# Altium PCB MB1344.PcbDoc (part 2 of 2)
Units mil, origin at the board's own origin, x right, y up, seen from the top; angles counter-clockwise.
Board outline 2760.94 x 3253.06 mil, 2 copper layers (Top Layer, Bottom Layer), stack 61.811 mil thick; 133 components, 124 nets, 521 pads, 490 vias.
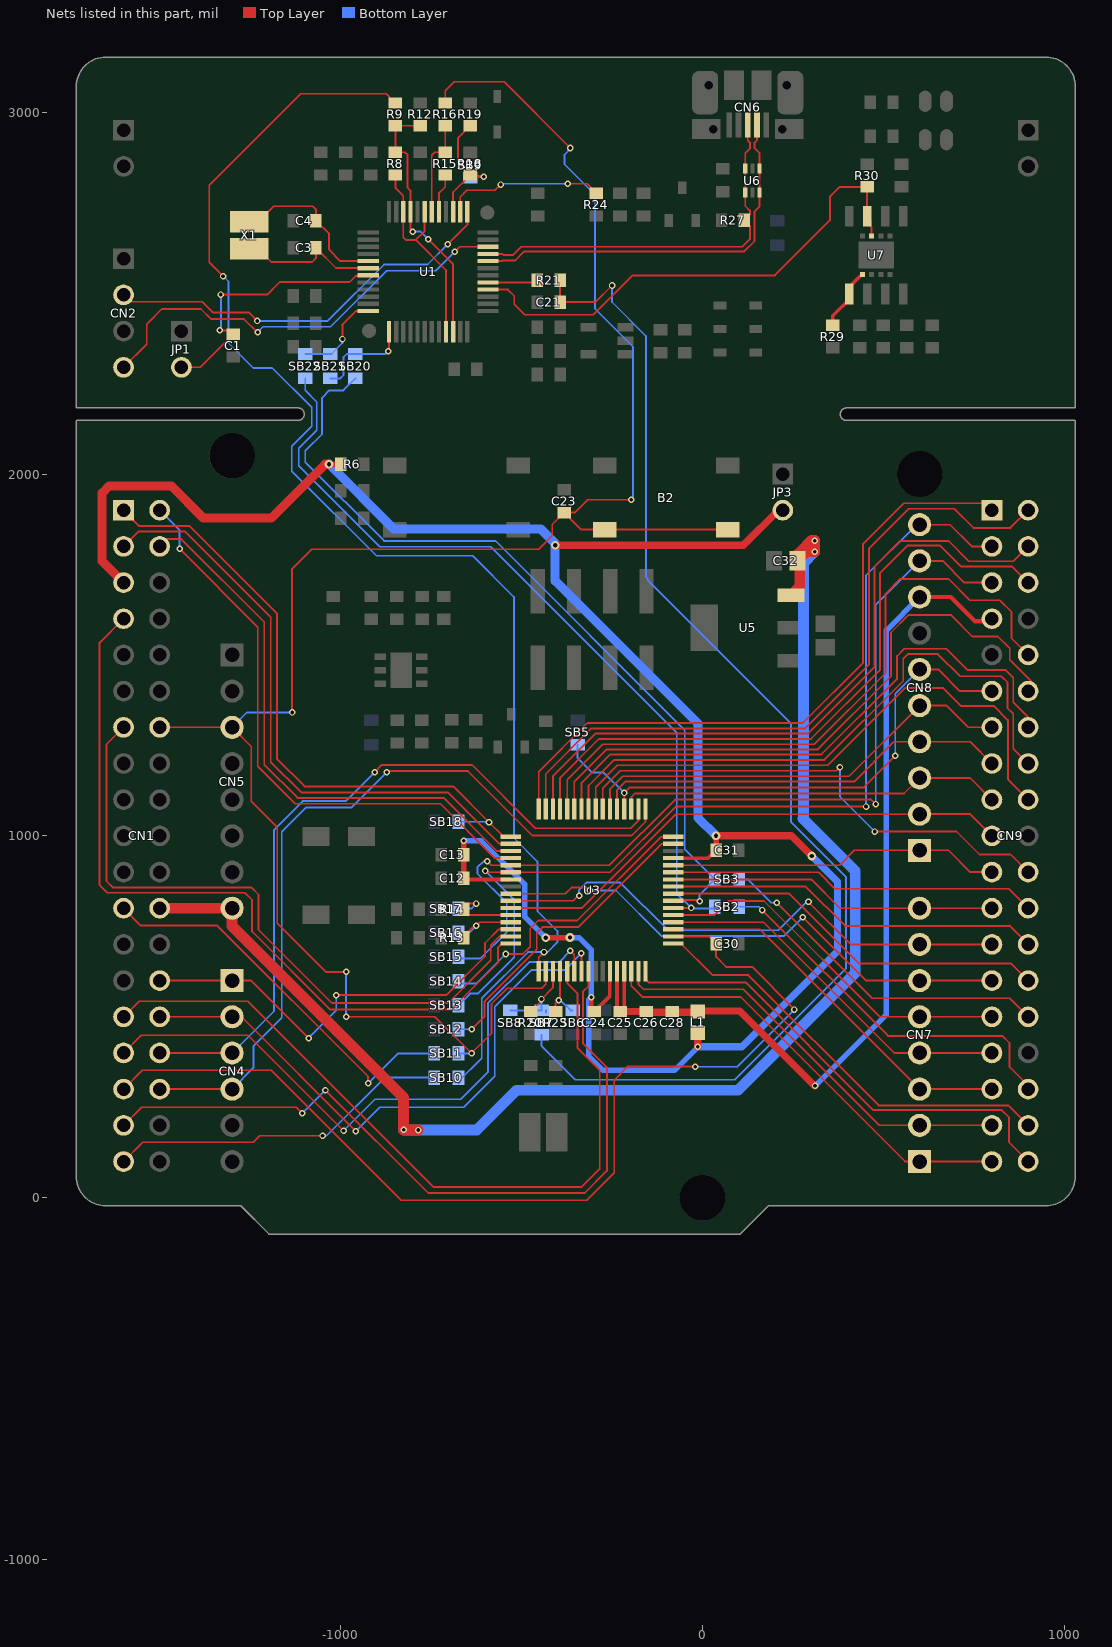
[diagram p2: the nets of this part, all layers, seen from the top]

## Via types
v1: diameter 18, hole 10, Top Layer to Bottom Layer, tented both sides, 474 vias
v2: diameter 24, hole 12, Top Layer to Bottom Layer, tented both sides, 12 vias
v3: diameter 23.62, hole 7.87, Top Layer to Bottom Layer, 4 vias

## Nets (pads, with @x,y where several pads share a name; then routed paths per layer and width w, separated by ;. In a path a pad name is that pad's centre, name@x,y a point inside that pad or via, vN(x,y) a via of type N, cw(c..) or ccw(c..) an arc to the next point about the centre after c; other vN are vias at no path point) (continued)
NetR18_1: R18.1 R19.2 SB9.2 U1.39 | length 356.5
  Top Layer w5: U1.39@-689.1,2724.35 -689.1,2779.4 R18.1@-646.5,2822 ; R19.2@-642,2962.5 -676,2928.5 -676,2860.5 R18.1@-642,2826.5 -637.5,2822 v1(-605,2822)
  Bottom Layer w5: SB9.2@-642,2819.25 -639.25,2822 v1(-605,2822)
NetR21_1: R21.1 U1.29 | length 138.9
  Top Layer w5: U1.29@-592.65,2529.47 -463.02,2529.47 R21.1@-456.5,2536
NetSB20_2: SB20.2 SB21.2 U1.13 | length 276.1
  Top Layer w5: v1(-868,2339) -866.27,2340.73 U1.13@-866.27,2393.65
  Bottom Layer w5: SB21.2@-1028.5,2264.25 -1000.75,2264.25 -992,2273 -992,2323 -983.25,2331.75 SB20.2@-959,2331.75 -875.25,2331.75 v1(-868,2339)
NetSB21_1: SB21.1 SB22.2 U1.12 | length 254.6
  Top Layer w5: v1(-995,2373) -995,2411 -996,2412 -957.27,2450.73 U1.12@-923.35,2450.73
  Bottom Layer w5: SB22.2@-1098,2331.75 SB21.1@-1028.5,2331.75 -1025.25,2331.75 -995,2362 v1(-995,2373)
PA0: CN1.37 SB10.1 | length 954.3
  Top Layer w5: CN1.37@-1600,100 -1547,153 -1242,153 -1224,171 v1(-1050,171)
  Bottom Layer w5: v1(-1050,171) -1039,171 -878,332 SB10.1@-741.75,332
PA1: CN1.23 SB11.1 | length 1104.1
  Top Layer w5: CN1.23@-1600,800 -1552,752 -1341,752 -924,335 v1(-924,316)
  Bottom Layer w5: v1(-924,316) -841.29,398.71 SB11.1@-741.75,398.71
PA2: R20.2 SB7.2 SB8.1 U3.3 | length 261.9
  Top Layer w5: R20.2@-475,514.46 -445,544.46 v1(-445,549) -413.27,580.73 U3.3@-413.27,625.59
  Bottom Layer w5: SB8.1@-531,517.5 SB7.2@-444.67,517.5 -444.67,548.67 v1(-445,549) ; SB7.2@-432.33,511.75 SB7.2@-432.33,519
PA3: R23.1 SB6.1 U3.4 | length 166.7
  Top Layer w5: R23.1@-406,514.46 -406,537 v1(-397,546) -393.58,549.42 U3.4@-393.58,625.59
  Bottom Layer w5: v1(-397,546) -393,546 -364.5,517.5 SB6.1@-358.33,517.5
PA4: CN1.29 U3.5 | length 2149.8
  Top Layer w5: CN1.29@-1600,500 -1557,543 -1257,543 -744,30 -334,30 -284,80 -284,352 -345,413 -345,564 -373.9,592.9 U3.5@-373.9,625.59
PA5: CN1.31 U3.6 | length 1742.7
  Top Layer w5: CN1.31@-1600,400 -1551,449 -1256,449 v1(-992,185) ; v1(-365,682) -354.21,671.21 U3.6@-354.21,625.59
  Bottom Layer w5: v1(-992,185) -905,272 -668,272 -593,347 -593,537 -479,651 -396,651 v1(-365,682)
PA6: CN1.30 CN4.2 U3.7 | length 1662.3
  Top Layer w5: CN1.30@-1500,500 CN4.2@-1300,500 -1274,500 v1(-958,184) ; U3.7@-334.53,625.59 v1(-334.53,675.47)
  Bottom Layer w5: v1(-958,184) -892,250 -660,250 -574,336 -574,528 -473,629 -381,629 v1(-334.53,675.47)
PA7: CN1.35 U3.8 | length 2118.4
  Top Layer w5: CN1.35@-1600,200 -1550,250 -1123,250 v1(-1106,233) ; v1(-1042,297) -758,13 -325,13 -264,74 -264,360 -330,426 -330,570 -314.84,585.16 U3.8@-314.84,625.59
  Bottom Layer w5: v1(-1106,233) v1(-1042,297)
PB0: SB12.1 U3.31 | length 857.3
  Top Layer w5: v1(-638,465.43) -602,501.43 -602,542.4 -458,686.4 -458,732 -442,748 -343,748 -113.05,977.95 U3.31@-80.59,977.95 U3.31@-80.17,978.37
  Bottom Layer w5: SB12.1@-674.25,465.43 v1(-638,465.43)
PB1: SB14.1 U3.32 | length 792.4
  Top Layer w5: v1(-544,673.5) -496.5,673.5 -476,694 -476,744 -454,766 -346,766 -114.36,997.64 U3.32@-80.59,997.64 U3.32@-80.59,999.07
  Bottom Layer w5: SB14.1@-674.25,592 -625.5,592 v1(-544,673.5)
PB2: CN1.34 CN4.4 U3.33 | length 2177.5
  Top Layer w5: CN1.34@-1500,300 CN4.4@-1300,300 ; v1(-873,1176) -875,1176 -878,1179 -648,1179 -470,1001 -196,1001 -157.36,1039.64 U3.33@-157.36,1074.41
  Bottom Layer w5: CN4.4@-1300,300 -1241,359 -1241,419 -1163,497 -1163,1011 -1096,1078 -971,1078 v1(-873,1176)
PB3: CN1.32 CN4.3 U3.34 | length 2059.8
  Top Layer w5: CN1.32@-1500,400 CN4.3@-1300,400 ; v1(-906,1176) -886,1196 -637,1196 -462,1021 -198,1021 -177.05,1041.95 U3.34@-177.05,1074.41
  Bottom Layer w5: CN4.3@-1300,400 -1184,516 -1184,1017 -1105,1096 -986,1096 v1(-906,1176)
PB4: CN8.3 CN9.17 U3.35 | length 1076.3
  Top Layer w5: U3.35@-196.73,1074.41 -196.73,1107.27 -187,1117 557,1117 CN8.3@600,1160 740,1160 CN9.17@800,1100
PB5: CN8.6 CN9.11 SB5.1 U3.36 | length 1533.4
  Top Layer w5: U3.36@-216.42,1074.41 v1(-216.42,1118.58) -201,1134 446,1134 v1(533,1221) ; CN8.6@600,1460 651,1460 711,1400 CN9.11@800,1400
  Bottom Layer w5: SB5.1@-345,1252.25 -345,1215 -305,1175 -272.83,1175 v1(-216.42,1118.58) ; v1(533,1221) 533,1393 CN8.6@600,1460
PB6: CN8.4 CN9.15 U3.37 | length 1168.6
  Top Layer w5: U3.37@-236.1,1074.41 -236.1,1126.9 -213,1150 419,1150 529,1260 CN8.4@600,1260 740,1260 CN9.15@800,1200
PB7: CN8.5 CN9.13 U3.38 | length 1231
  Top Layer w5: U3.38@-255.79,1074.41 -255.79,1129.21 -220,1165 405,1165 CN8.5@600,1360 675,1360 735,1300 CN9.13@800,1300
PC0: CN8.9 CN9.5 SB15.2 U3.53 | length 2515.9
  Top Layer w5: v1(-595,930) -583.9,918.9 U3.53@-529.41,918.9 -257.1,918.9 -75.63,1100.37 466.63,1100.37 v1(479,1088) ; CN8.9@600,1760 664,1760 724,1700 CN9.5@800,1700
  Bottom Layer w5: SB15.2@-674.25,661 -614,661 -541,734 -541,815 -622,896 -622,913 -605,930 v1(-595,930) ; v1(479,1088) 479,1639 CN8.9@600,1760
PC1: CN8.10 CN9.3 SB13.2 U3.54 | length 2679.1
  Top Layer w5: v1(-600,903) -596.21,899.21 U3.54@-529.41,899.21 -529.25,899.37 -255.63,899.37 -74,1081 v1(452,1081) ; CN8.10@600,1860 684,1860 744,1800 CN9.3@800,1800
  Bottom Layer w5: SB13.2@-674.25,532.14 -642.39,564 -621,564 -520,665 -520,823 v1(-600,903) ; v1(452,1081) 452,1720 592,1860 CN8.10@600,1860
PC2: CN7.6 CN9.27 U3.57 | length 1485.9
  Top Layer w5: U3.57@-529.41,840.16 -378.84,840.16 -362,857 -320,857 v1(-312,849) ; v1(277,775) 277.33,775 452.33,600 CN7.6@600,600 CN9.27@800,600
  Bottom Layer w5: v1(-312,849) -239,849 -113,723 225,723 v1(277,775)
PC3: CN7.7 CN9.25 U3.58 | length 1497.2
  Top Layer w5: U3.58@-529.41,820.47 -357.53,820.47 -344,834 v1(-341,834) ; v1(293,818) 293,817 410,700 CN7.7@600,700 CN9.25@800,700
  Bottom Layer w5: v1(-341,834) -341,851 -321,871 -227,871 -95,739 209,739 288,818 v1(293,818)
PC4: CN8.2 CN9.19 U3.59 | length 1462.1
  Top Layer w5: U3.59@-529.41,800.79 -332.81,800.79 -292.63,840.98 -292.63,841.37 -74.37,1059.63 600,1059.63 CN8.2@600,1060 740,1060 CN9.19@800,1000
PC5: R14.1 SB17.1 U3.60 | length 232.9
  Top Layer w5: v1(-625,813) -643.5,813 R14.1@-659.5,797 -643.61,781.1 U3.60@-529.41,781.1
  Bottom Layer w5: SB17.1@-674.25,799 -639,799 v1(-625,813)
PC6: R13.1 SB16.1 U3.61 | length 207.7
  Top Layer w5: R13.1@-659.5,719 -659.5,723.5 -631,752 v1(-625,752) -615.58,761.42 U3.61@-529.41,761.42
  Bottom Layer w5: SB16.1@-674.25,732.28 -644.72,732.28 v1(-625,752)
PC7: CN1.28 CN4.1 U3.62 | length 1207.9
  Top Layer w5: CN1.28@-1500,600 CN4.1@-1300,600 -1247,600 v1(-1088,441) ; v1(-1012,560) -708,560 -601,667 -601,704 -563.27,741.73 U3.62@-529.41,741.73
  Bottom Layer w5: v1(-1088,441) -1088,442 -1012,518 v1(-1012,560)
PD0: CN9.26 U3.25 | length 1046.8
  Top Layer w5: U3.25@-80.59,859.84 285.16,859.84 394,751 849,751 CN9.26@900,700
PD1: CN7.8 CN9.23 U3.26 | length 913.5
  Top Layer w5: U3.26@-80.59,879.53 300.47,879.53 380,800 CN7.8@600,800 CN9.23@800,800
PD2: CN9.24 U3.27 | length 1021.7
  Top Layer w5: U3.27@-80.59,899.21 320.79,899.21 366,854 846,854 CN9.24@900,800
PD3: CN8.1 CN9.21 U3.28 | length 922.5
  Top Layer w5: U3.28@-80.59,918.9 378.9,918.9 420,960 CN8.1@600,960 680,960 740,900 CN9.21@800,900
PD4: CN9.6 U3.45 | length 1844.8
  Top Layer w5: U3.45@-393.58,1074.41 -393.58,1160.42 -286,1268 300,1268 491,1459 491,1727 566.26,1802.26 656.74,1802.26 715,1744 856,1744 CN9.6@900,1700
PD5: CN9.4 U3.46 | length 1875.5
  Top Layer w5: U3.46@-413.27,1074.41 -413.27,1164.73 -295,1283 292,1283 475,1466 475,1743 547.14,1815.14 679.86,1815.14 736,1759 859,1759 CN9.4@900,1800
PD6: CN9.2 U3.47 | length 1963.5
  Top Layer w5: U3.47@-432.95,1074.41 -432.95,1171.05 -307,1297 284,1297 460,1473 460,1794 570,1904 696,1904 749,1851 851,1851 CN9.2@900,1900
PD7: CN9.1 U3.48 | length 1862.8
  Top Layer w5: U3.48@-452.64,1074.41 -452.64,1177.36 -318,1312 277,1312 444,1479 444,1807 556,1919 781,1919 CN9.1@800,1900
PE0: CN7.3 CN9.33 U3.19 | length 1063.6
  Top Layer w5: U3.19@-80.59,741.73 158.27,741.73 CN7.3@600,300 CN9.33@800,300
PE1: CN7.4 CN9.31 U3.20 | length 1030.3
  Top Layer w5: U3.20@-80.59,761.42 168.58,761.42 530,400 CN7.4@600,400 CN9.31@800,400
PE2: CN7.5 CN9.29 U3.21 | length 1029.3
  Top Layer w5: U3.21@-80.59,781.1 33.1,781.1 72,820 170,820 490,500 CN7.5@600,500 CN9.29@800,500
PE3: CN9.34 SB2.2 | length 1051.5
  Top Layer w5: v1(165,795) 513,447 829,447 848.5,427.5 848.5,361.5 900,310 CN9.34@900,300
  Bottom Layer w5: SB2.2@101.75,804 156,804 v1(165,795)
PE4: CN9.30 SB3.2 | length 955.5
  Top Layer w5: v1(205,815) 469,551 849,551 CN9.30@900,500
  Bottom Layer w5: SB3.2@101.75,879.53 125.47,879.53 190,815 v1(205,815)
PE5: CN9.28 U3.24 | length 1080.4
  Top Layer w5: U3.24@-80.59,840.16 -80.59,840.37 239.63,840.37 433,647 853,647 CN9.28@900,600
PE6: CN1.13 U3.63 | length 1859.3
  Top Layer w5: CN1.13@-1600,1300 -1647,1253 -1647,875 -1629,857 -1246,857 -1227,838 -1227,741 -1024,538 -703,538 -585,656 -585,698 -560.95,722.05 U3.63@-529.41,722.05
PE7: CN1.7 U3.64 | length 2193.5
  Top Layer w5: CN1.7@-1600,1600 -1666,1534 -1666,864 -1645,843 -1265,843 -1245,823 -1245,736 -1029,520 -695,520 -565,650 -565,692 -554.64,702.36 U3.64@-529.41,702.36
PF0: CN9.22 U3.39 | length 1432
  Top Layer w5: U3.39@-275.47,1074.41 -275.47,1131.53 -227,1180 370,1180 v1(380,1190) ; v1(476,1012) 702,1012 765.5,948.5 851.5,948.5 CN9.22@900,900 CN9.22@900,907
  Bottom Layer w5: v1(380,1190) 380,1108 v1(476,1012)
PF1: CN9.18 U3.40 | length 1593.2
  Top Layer w5: U3.40@-295.16,1074.41 -295.16,1134.84 -235,1195 346,1195 560,1409 664,1409 714,1359 805,1359 844,1320 844,1156 CN9.18@900,1100
PF4: CN9.16 U3.41 | length 1689.3
  Top Layer w5: U3.41@-314.84,1074.41 -314.84,1139.16 -244,1210 337,1210 555,1428 555,1490 567.26,1502.26 650.74,1502.26 712,1441 826,1441 843,1424 843,1353 859,1337 859,1241 CN9.16@900,1200
PF5: CN9.14 U3.42 | length 1642.5
  Top Layer w5: U3.42@-334.53,1074.41 -334.53,1145.47 -255,1225 329,1225 538,1434 538,1497 558,1517 674,1517 733,1458 838,1458 859.1,1436.9 859.1,1368.9 900,1328 CN9.14@900,1300
PF6: CN9.12 U3.43 | length 1712
  Top Layer w5: U3.43@-354.21,1074.41 -354.21,1149.79 -265,1239 319,1239 521,1441 521,1562 569,1610 687,1610 746,1551 816,1551 849,1518 849,1487 909.1,1426.9 CN9.12@909.1,1409.1
PF7: CN9.10 U3.44 | length 1842.5
  Top Layer w5: U3.44@-373.9,1074.41 -373.9,1155.1 -276,1253 309,1253 506,1450 506,1669 547,1710 680,1710 739,1651 822,1651 854,1619 854,1546 CN9.10@900,1500
PG0: CN7.1 CN9.37 U3.14 | length 1237.8
  Top Layer w5: U3.14@-196.73,625.59 -196.73,585.73 -166,555 105,555 560,100 CN7.1@600,100 CN9.37@800,100
PG1: CN7.2 CN9.35 U3.15 | length 1174.2
  Top Layer w5: U3.15@-177.05,625.59 -177.05,590.05 -163,576 113,576 489,200 CN7.2@600,200 CN9.35@800,200
PG2: CN9.38 U3.16 | length 1328.5
  Top Layer w5: U3.16@-157.36,625.59 -157.36,603.36 -149,595 119,595 471.74,242.26 826.74,242.26 847,222 847,153 CN9.38@900,100
PG3: CN9.36 U3.17 | length 1188.7
  Top Layer w5: U3.17@-80.59,702.36 -59.36,702.36 27.87,615.13 126.87,615.13 486.86,255.14 844.86,255.14 CN9.36@900,200
PG4: CN1.1 SB18.1 U3.49 | length 1764.5
  Top Layer w5: CN1.1@-1600,1900 -1556,1856 -1417,1856 -1176,1615 -1176,1213 -1099.63,1136.63 -688.63,1136.63 v1(-590,1038) -549.64,997.64 U3.49@-529.41,997.64
  Bottom Layer w5: SB18.1@-674.25,1039 -591,1039 v1(-590,1038)
PG5: CN1.3 U3.50 | length 1679.4
  Top Layer w5: CN1.3@-1600,1800 -1559,1841 -1430,1841 -1193,1604 -1193,1204 -1109,1120 -704,1120 -561.95,977.95 U3.50@-529.41,977.95
PG6: CN1.4 U3.51 | length 1566.6
  Top Layer w5: CN1.4@-1500,1800 -1480,1820 -1440,1820 -1211,1591 -1211,1197 -1119,1105 -715,1105 -568.27,958.27 U3.51@-529.41,958.27
PG7: CN1.2 U3.52 | length 1624.8
  Top Layer w5: v1(-1445,1793) -1229,1577 -1229,1192 -1126,1089 -724,1089 -573.58,938.58 U3.52@-529.41,938.58
  Bottom Layer w5: CN1.2@-1500,1900 -1445,1845 v1(-1445,1793)
PWR_ENN: R30.2 U1.28 U7.3 | length 1414.9
  Top Layer w5: U1.28@-592.65,2509.79 -537.79,2509.79 -520,2492 -520,2469 -491,2440 -302,2440 -193,2549 200,2549 352,2701 352,2766 379.5,2793.5 R30.2@455,2793.5 U7.3@455,2712.28 455,2711.3 464,2702.3 464,2684 467.2,2680.8 U7.3@467.2,2658.15
SET: R29.2 U7.5 | length 168.3
  Top Layer w10: R29.2@360,2411.5 360,2437 405,2482 405,2516 U7.5@436.91,2547.91
STLINK_SWCLK: CN2.2 U1.37 | length 1125.5
  Top Layer w5: CN2.2@-1600,2495 -1581,2476 -1382,2476 -1352,2446 -1253,2446 v1(-1230,2423) ; v1(-704,2635) -649.73,2689.27 U1.37@-649.73,2724.35
  Bottom Layer w5: v1(-1230,2423) -1036,2423 -880,2579 -760,2579 v1(-704,2635)
STLINK_SWDIO: CN2.4 U1.34 | length 1230.5
  Top Layer w5: CN2.4@-1600,2295 -1536,2359 -1536,2414 -1494,2456 -1386,2456 -1358,2428 -1267,2428 -1231,2392 v1(-1229.6,2392) ; v1(-685,2614) -671.1,2627.9 U1.34@-592.65,2627.9
  Bottom Layer w5: v1(-1229.6,2392) -1214.6,2407 -1028,2407 -873,2562 -737,2562 v1(-685,2614)
STLINK_USB_D_N: CN6.2 U1.32 U6.1 U6.6 | length 1094.8
  Top Layer w5: U1.32@-592.65,2588.53 -554.47,2588.53 -553,2590 -517.79,2590 -492.66,2615.13 115.13,2615.13 144,2644 144,2726 157.69,2739.69 U6.6@157.69,2777.54 U6.1@157.69,2844.46 157.69,2886.31 143.87,2900.13 143.87,2915.87 150.59,2922.59 CN6.2@150.59,2965
STLINK_USB_D_P: CN6.3 R27.2 U1.33 U6.3 U6.4 | length 1085.1
  Top Layer w5: U1.33@-592.65,2608.21 -553,2608.21 -549.79,2605 -524,2605 -501,2628 109.79,2628 131.13,2649.33 131.13,2685.37 R27.2@115.5,2701 131.13,2716.63 131.13,2727.87 118.31,2740.69 U6.4@118.31,2777.54 U6.3@118.31,2844.46 118.31,2886.31 131,2899 131,2916 125,2922 CN6.3@125,2965
STLK_OSC_IN: C4.1 U1.5 X1.2 | length 453
  Top Layer w5: X1.2@-1252,2697.4 -1227.6,2697.4 -1185,2740 -1077,2740 -1068.5,2731.5 C4.1@-1068.5,2700 -1032,2663.5 -1032,2620 -1000.53,2588.53 U1.5@-923.35,2588.53
STLK_OSC_OUT: C3.1 U1.6 X1.1 | length 399.9
  Top Layer w5: X1.1@-1252,2622.6 -1228.6,2622.6 -1192,2586 -1079,2586 -1068.5,2596.5 C3.1@-1068.5,2625 -1012.88,2569.37 -923.89,2569.37 U1.6@-923.35,2568.84
STLK_RST: C1.2 JP1.2 U1.7 | length 752.2
  Top Layer w5: JP1.2@-1440,2295 -1388.5,2295 C1.2@-1297,2386.5 -1307.5,2397 v1(-1334,2397) ; v1(-1331,2496) -1203,2496 -1168.37,2530.63 -975.37,2530.63 -958.87,2547.13 -925.39,2547.13 U1.7@-923.35,2549.16
  Bottom Layer w5: v1(-1334,2397) -1331,2400 v1(-1331,2496)
SWIM: R8.1 R9.2 R12.1 U1.22 U1.45 | length 731.8
  Top Layer w5: v1(-801,2670) -807.21,2676.21 U1.45@-807.21,2724.35 -807.21,2783.21 -815,2791 -815,2882 -822.5,2889.5 R8.1@-848.5,2889.5 R9.2@-848.5,2962.5 R12.1@-779.67,2962.5 ; v1(-758,2649) -689.1,2580.1 U1.22@-689.1,2393.65
  Bottom Layer w5: v1(-801,2670) -779,2670 v1(-758,2649)
SWIM_IN: R8.2 U1.21 U1.43 U1.46 | length 594.5
  Top Layer w5: R8.2@-848.5,2826.5 -848.5,2790.6 -826.9,2769 U1.46@-826.9,2724.35 -826.9,2653.9 -819.95,2646.95 -792.05,2646.95 ; U1.43@-767.84,2724.35 -767.84,2671.16 -792.05,2646.95 ; U1.21@-708.79,2393.65 -708.79,2563.69 -792.05,2646.95
SWIM_RST: R15.1 R16.2 U1.42 | length 270.4
  Top Layer w5: U1.42@-748.16,2724.35 -748.16,2880.84 -739.5,2889.5 R15.1@-710.83,2889.5 R16.2@-710.83,2962.5
SWIM_RST_IN: R15.2 U1.41 | length 109.5
  Top Layer w5: U1.41@-728.47,2724.35 -728.47,2775.53 -710.83,2793.17 R15.2@-710.83,2826.5
T_MCO: C21.2 R21.2 SB7.1 | length 3417.5
  Top Layer w5: R21.2@-393.5,2536 C21.2@-393.5,2475 -296,2475 v1(-250,2521)
  Bottom Layer w5: SB7.1@-444.67,450 -444.67,418.67 -352,326 89,326 397,634 397,886 245,1038 245,1310 -151,1706 -151,1710.19 -156,1715.19 -156,2381.31 -250,2475.31 v1(-250,2521)
T_NRST: B2.1 B2.2 C23.2 CN1.14 CN5.3 R16.1 SB11.2 U3.2 | length 5566.6
  Top Layer w5: CN1.14@-1500,1300 CN5.3@-1300,1300 -1247,1247 -1247,1096 -1175,1024 -1175,758 -1041,624 v1(-985,624) ; v1(-1134,1341) -1134,1738 -1080,1792 -453,1792 -415,1830 -415,1860.5 C23.2@-382,1893.5 ; v1(-985,500) -739.57,500 v1(-638.29,398.71) -583,454 -583,536 -540,579 -444,579 -443,580 -432.95,590.08 U3.2@-432.95,625.59 ; R16.1@-710.83,3025.5 -710.83,3059 -685.83,3084 -548,3084 v1(-365,2901) ; v1(-197,1929) -317,1929 -352.5,1893.5 C23.2@-382,1893.5 ; B2.1@70.28,1846.42 B2.2@-270.28,1846.42 -334.91,1846.42 C23.2@-382,1893.5
  Bottom Layer w5: CN5.3@-1300,1300 -1259,1341 v1(-1134,1341) ; v1(-985,500) v1(-985,624) ; SB11.2@-674.25,398.71 v1(-638.29,398.71) ; v1(-365,2901) -365,2898.99 -381.37,2882.62 -381.37,2856.22 -297,2771.84 -297,2456.49 -192,2351.49 -192,1934 v1(-197,1929)
T_SWIM: R9.1 SB10.2 U3.1 | length 3946.5
  Top Layer w5: v1(-1325,2547) -1363,2585 -1363,2798 -1110,3051 -874,3051 R9.1@-848.5,3025.5 ; U3.1@-452.64,625.59 -452.64,664.36 v1(-438,679)
  Bottom Layer w5: v1(-1325,2547) -1310,2532 -1310,2362 -1241,2293 -1189,2293 -1080,2184 -1080,2132 -1135,2077 -1135,2008 -901,1774 -635,1774 -521,1660 -521,994 -456,929 -456,792 -401,737 -401,706 -428,679 v1(-438,679) -482,679 -610,551 -610,385.6 -674.25,321.35 SB10.2@-674.25,316
T_VCP_RX: SB2.1 SB22.1 U3.22 | length 2243.7
  Top Layer w5: U3.22@-80.59,800.79 v1(-31.21,800.79)
  Bottom Layer w5: SB22.1@-1098,2264.25 -1098,2231 -1066,2199 -1066,2121 -1116,2071 -1116,2023 -892,1799 -585,1799 -71,1285 -71,840.57 v1(-31.21,800.79) -30.05,799.63 29.88,799.63 SB2.1@34.25,804
T_VCP_TX: SB3.1 SB20.1 U3.23 | length 2268.3
  Top Layer w5: U3.23@-80.59,820.47 -80.59,822.37 -11.37,822.37 v1(-8,819)
  Bottom Layer w5: SB20.1@-959,2264.25 -992.25,2231 -1031,2231 -1051.37,2210.63 -1051.37,2110.63 -1098,2064 -1098,2033 -880,1815 -572,1815 -49,1292 -49,962.78 SB3.1@34.25,879.53 -8,837.28 v1(-8,819)
USB_RENUMN: R24.2 U1.38 | length 443.5
  Top Layer w5: U1.38@-669.42,2724.35 -669.42,2765.58 -651,2784 -574,2784 v1(-558,2800) ; v1(-372,2802) -319.01,2802 R24.2@-293,2775.99
  Bottom Layer w5: v1(-558,2800) -556,2802 v1(-372,2802)
VDD: C12.1 C13.1 C24.1 C31.1 CN1.5 JP3.2 L1.1 R6.2 U3.11 U3.29 U3.55 | length 6263
  Top Layer w10: -565,879.53 U3.55@-529.41,879.53 ; C24.1@-299,514.46 -255.79,557.68 U3.11@-255.79,625.59 ; U3.29@-80.59,938.58 16.09,938.58 C31.1@37.5,960
  Top Layer w12: C12.1@-653.03,879.53 -565,879.53 ; v1(-307,554) -307,522.46 C24.1@-299,514.46
  Top Layer w15: v2(-1032,2027) R6.2@-1003.5,2027 ; C12.1@-659.5,883 C13.1@-659.5,948 v1(-659.5,986.5) ; v2(-433,718) -432,719 v2(-366,719) ; C31.1@37.5,960 v2(37.5,1000)
  Top Layer w20: v2(-407,1803) 113,1803 210,1900 JP3.2@222,1900 ; v1(-13,417) L1.1@-13,455.47 ; v2(37.5,1000) 245.96,1000 v2(301.8,944.16)
  Top Layer w25: CN1.5@-1600,1700 -1659,1759 -1659,1947 -1639,1967 -1468,1967 -1379,1878 -1192,1878 -1043,2027 v2(-1032,2027)
  Bottom Layer w15: v1(-659.5,986.5) -611.5,986.5 -491,866 -491,776 v2(-433,718) ; v2(-366,719) -341,719 -307,685 v1(-307,554) -314.5,546.5 -314.5,391.5 -275,352 -78,352 v1(-13,417)
  Bottom Layer w20: v1(-13,417) 109,417 373,681 373,872.96 v2(301.8,944.16)
  Bottom Layer w25: v2(-1032,2027) -853,1848 -447,1848 -407,1808 v2(-407,1803) -407,1705 -13,1311 -13,1050.5 v2(37.5,1000)
VDDA: C25.1 C26.1 C28.1 CN8.8 CN9.7 L1.2 U3.12 U3.13 | length 2561
  Top Layer w10: U3.12@-236.1,625.59 -236.1,523.57 C25.1@-227,514.46 -216.42,525.05 U3.13@-216.42,625.59
  Top Layer w12: CN8.8@600,1660 686,1660 753,1593 793,1593 CN9.7@800,1600
  Top Layer w15: C26.1@-159.97,514.46 -158,512.5 C26.1@-153.03,512.5
  Top Layer w20: C25.1@-227,514.46 C26.1@-159.97,514.46 ; C26.1@-155,514.46 -153.03,512.5 -17,512.5 -13,516.5 -12.5,516 103,516 310,309 v1(311,309)
  Bottom Layer w15: v1(311,309) 508,506 508,1568 CN8.8@600,1660
VIN: C32.2 CN1.24 CN5.8 U5.3 | length 4107.5
  Top Layer w30: CN1.24@-1500,800 CN5.8@-1300,800 -1300,751 -826,277 v1(-826,188) -825,187 v1(-786,187) ; U5.3@245.08,1665.55 269,1689.47 269,1753.48 C32.2@262.48,1760 ; C32.2@262.48,1760 287.48,1785 ; C32.2@262.48,1760 C32.2@262.48,1768.48 ; C32.2@262.48,1768.48 C32.2@279,1785 ; C32.2@262.48,1768.48 262.48,1777.48 C32.2@270,1785 ; C32.2@270,1785 301,1816 v1(310,1816) ; C32.2@270,1785 C32.2@279,1785 ; C32.2@279,1785 287.48,1785 ; C32.2@279,1785 v1(310,1816) ; 287.48,1785 v1(310,1785) v1(310,1816)
  Bottom Layer w30: v1(-826,188) -825,187 v1(-786,187) -624,187 -514,297 97.88,297 421.44,620.56 421.44,622.56 422.37,623.49 422.37,902.63 277,1048 279.03,1050.03 ; 279,1050.06 279,1754 v1(310,1785) v1(310,1816)
VLCD: C30.1 CN1.33 U3.18 | length 2833.2
  Top Layer w5: CN1.33@-1600,300 -1548,352 -1192,352 -833,-7 -320,-7 -244,69 -244,325 -206,363 v1@-20,363 ; U3.18@-80.59,722.05 17.46,722.05 C30.1@37.5,702 37.5,665.5 65,638 137,638 254,521 v1(254,520)
  Bottom Layer w5: v1(-20,362) 96,362 v1(254,520)
pads on no net: 1.1 CN1.9 CN1.10 CN1.11 CN1.21 CN1.26 U1.0 U1.4 U1.11 U1.14 U1.15 U1.16 U1.17 U1.18 U1.19 U1.25 U1.26 U1.27 U1.31 U1.40 U2.3 U2.5 X2.2 X2.3

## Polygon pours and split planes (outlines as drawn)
NetC27_2 on Top Layer "NONET_L-01_P-001" (solid, remove dead copper, pour order 0): -236,2297 -219,2280 42,2280 64.29,2302.29 64.29,2470.71 55,2480 -15,2480 -20,2475 -20,2356 -25,2351 -138,2351 -145,2358 -145,2435 -165,2455 -225,2455 -236,2444
NetC7_2 on Top Layer "NONET_L-01_P-001" (solid, remove dead copper, pour order 8): -965,1385 -965,1326 -939,1300 -731,1300.01 -731,1432 -792.91,1432 -792.91,1385
5V on Top Layer "NONET_L-01_P-001" (solid, remove dead copper, pour order 18): -1104,1194 -1076,1166 -987,1166 -969,1184 -969,1248 -1015,1294 -1015,1419 -961,1473 -961,1529 -997,1565 -1044,1565 -1104,1505
5V on Top Layer "NONET_L-01_P-001" (solid, remove dead copper, pour order 6): -790,1614 -790,1482 -697,1482 -697,1534 -685,1546 -639.55,1546 -570.62,1614 -441,1614 -441,1706 -606,1706 -698,1614
GND on Top Layer "NONET_L-01_P-001" (solid, remove dead copper, pour order 20): -1718.73,-100.2 1030.47,-100.19 1030.47,3162 -1718.73,3162
GND on Bottom Layer "NONET_L-01_P-001" (solid, remove dead copper, pour order 22): -1730.47,3152.12 -1730.47,-160 1030.46,-160 1030.47,3152.12
5V on Bottom Layer "NONET_L-01_P-001" (solid, remove dead copper, pour order 14): -632,1645 -632,1584 -651,1565 -866,1565 -1013,1418 -1051,1418 -1096,1463 -1096,1512 -939,1669 -656,1669
NetC7_2 on Bottom Layer "NONET_L-01_P-001" (solid, remove dead copper, pour order 10): -966,1379 -966,1318 -952.75,1304.75 -872,1304.75 -872,1379
3V3 on Bottom Layer "NONET_L-01_P-001" (solid, remove dead copper, pour order 12): -1325,1456 -1325,1179 -1229,1179 -1152,1256 -1032,1256 -961,1185 -888,1185 -871,1202 -871,1269 -949,1269 -1136,1456
5V on Bottom Layer "NONET_L-01_P-001" (solid, remove dead copper, pour order 16): -1325,1166 -1325,1024 -1214,1024 -1122,1116 -1024,1116 -1012,1128 -1012,1199 -1044,1231 -1130,1231 -1195,1166

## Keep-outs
Keep-Out Layer:
  lines w5: 102.76,-98.43 -1196.46,-98.43 -1275.2,-19.69 -1280.32,-19.69 -1649.21,-19.69 cw(c-1649.21,59.05) -1727.95,59.05 -1727.95,2145.67 -1117.72,2145.67 ccw(c-1117.72,2165.35) -1117.72,2185.04 -1727.95,2185.04 -1727.95,3070.87 cw(c-1649.21,3070.87) -1649.21,3149.61 949.21,3149.61 cw(c949.21,3070.87) 1027.95,3070.87 1027.95,2185.04 398.03,2185.04 ccw(c398.03,2165.35) 398.03,2145.67 1027.95,2145.67 1027.95,59.06 cw(c949.21,59.06) 949.21,-19.69 181.5,-19.69 102.76,-98.43 ; 102.76,-98.43 102.76,-98.43 ; -979.92,2145.67 cw(c-979.92,2165.35) -979.92,2185.04 -231.89,2185.04 cw(c-231.89,2165.35) -231.89,2145.67 -979.92,2145.67 ; -50,2145.67 cw(c-50,2165.35) -50,2185.04 238.58,2185.04 cw(c238.58,2165.35) 238.58,2145.67 -50,2145.67

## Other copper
Top Layer:
  pour cut-out: -322,514 -321,513 -321,400 -316,400 -269,353 -237,385 -19,385 2,406 -17,425 -17,512.5 -249.5,512.5 -251,511
  pour cut-out: 279,1605.7 308.3,1605.7 322,1592 322,1548 318.3,1544.3 279.3,1544.3
Bottom Layer:
  pour cut-out: -510.63,519.85 -510.63,542.15 -510.63,546 -465.87,546 -465.87,516.25 -509.53,516.25
  pour cut-out: -1082.88,2333.6 -1082.88,2355.9 -1082.88,2359.75 -1038.12,2359.75 -1038.12,2330 -1081.78,2330

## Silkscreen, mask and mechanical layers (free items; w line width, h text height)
Top Overlay:
  lines w5.91: -1050.73,-81.85 -263.33,-81.85 -263.33,75.63 -263.33,115 -1050.73,115 -1050.73,-81.85
  lines w6: -1349.21,1250 -1100,1250 -1100,1230 ; -1250.79,40.16 -1120,40.16 -1120,306 ; -1250.79,659.84 -1226.16,659.84 -1120,659.84 -1120,427 ; -1250.79,740.16 -1223.63,740.16 -1119,740.16 -1119,860 -1119,1060 -1100,1079 -1100,1100 ; -559,1468 -559,1438 -484.45,1438 -501,1451 ; -501,1428 -484.05,1437.68
  text "GND" at -1676,3018 h86.61
  text "GND" at 818,3018 h86.61
  text "USB STLink" at -429,2959 h86.61
  text "COM" at 797,2888 h86.61 r90
  text "SWD" at -1676,2669 h86.61
  text "USER" at -797,2060 h86.61
  text "RESET" at -218,2060 h86.61
  text "IDD" at 141,2060 h86.61
  text "SCL/D15" at 308.82,1841 h40
  text "PWR IN" at -390,1758 h40
  text "SDA/D14" at 298.54,1735 h40
  text "E5V" at -1430,1677 h40
  text "VDDA" at 394.71,1638 h40
  text "5V" at -538,1628 h40 r90
  text "GND" at -1430,1584 h40
  text "GND" at 430.32,1534 h40
  text "STL" at -538,1482 h40 r90
  text "SCK/D13" at 302.66,1431 h40
  text "IOREF" at -1230,1390 h40
  text "MISO/D12" at 288,1338 h40
  text "E5V" at -202,1283 h40 r90
  text "NRST" at -1230,1280 h40
  text "TIM/MOSI/D11" at 194.12,1235 h40
  text "5V_VIN" at -300,1208 h40 r90
  text "5V_CHG" at -58,1208 h40 r90
  text "3V3" at -1236,1175 h40
  text "TIM/CS/D10" at 227.25,1138 h40
  text "www.st.com/stm8nucleo" at -852,1132 h59.06
  text "PWR" at -1070,1110 h40 r90
  text "5V" at -1236,1080 h40
  text "TIM/D9" at 363.22,1036 h40
  text "GND" at -1236,980 h40
  text "IO/D8" at 393,938 h40
  text "GND" at -1236,875 h40
  text "IO/D7" at 393,778 h40
  text "VIN" at -1236,775 h40
  text "TIM/D6" at 361.38,677 h40
  text "A0" at -1236,581 h40
  text "TIM/D5" at 359.48,577 h40
  text "A1" at -1236,480 h40
  text "IO/D4" at 391.09,475 h40
  text "A2" at -1236,385 h40
  text "TIM/D3" at 359.48,377 h40
  text "NUCLEO-8L152R8" at 261,374 h60 r90
  text "AIN" at -1100,328 h40 r90
  text "IO/D2" at 393,283 h40
  text "A3" at -1236,280 h40
  text "A4" at -1236,180 h40
  text "TX/D1" at 391.28,175 h40
  text "MB1344C" at -1052,140 h60
  text "A5" at -1236,85 h40
  text "RX/D0" at 369.95,76 h40
Bottom Overlay:
  drawing of 550 lines, arcs and shapes, not listed
M1-Board Shape:
  lines w5: 102.76,-98.43 -1196.46,-98.43 -1275.2,-19.69 -1280.32,-19.69 -1649.21,-19.69 cw(c-1649.21,59.05) -1727.95,59.05 -1727.95,2145.67 -1117.72,2145.67 ccw(c-1117.72,2165.35) -1117.72,2185.04 -1727.95,2185.04 -1727.95,3070.87 cw(c-1649.21,3070.87) -1649.21,3149.61 949.21,3149.61 cw(c949.21,3070.87) 1027.95,3070.87 1027.95,2185.04 398.03,2185.04 ccw(c398.03,2165.35) 398.03,2145.67 1027.95,2145.67 1027.95,59.06 cw(c949.21,59.06) 949.21,-19.69 181.5,-19.69 102.76,-98.43 ; 102.76,-98.43 102.76,-98.43 ; -979.92,2145.67 cw(c-979.92,2165.35) -979.92,2185.04 -231.89,2185.04 cw(c-231.89,2165.35) -231.89,2145.67 -979.92,2145.67 ; -50,2145.67 cw(c-50,2165.35) -50,2185.04 238.58,2185.04 cw(c238.58,2165.35) 238.58,2145.67 -50,2145.67
M7-Top Info:
  lines w0.3: -2082,-958 -2053,-958 ; -2066,-968 -2029,-968 ; -2048,-958 -2028,-958 ; -2038,-963 -2027,-963 ; -2001,-958 -1997,-958 ; -1982,-963 -1971,-963
Drill Drawing:
  circle w10: c2563.62,1704.28 r20
  circle w10: c2563.62,1704.28 r33.33
  circle w10: c2563.62,1404.28 r33.33
  lines w0.05: -4103,391 -3883,391 ; -4103,3691 -3883,3691 ; -4103,6991 -3883,6991 ; -3069,8179 -2981,8267 ; -3069,8531 -2981,8619 ; -2981,8091 -2805,8267 ; -2981,8443 -2805,8619 ; -2893,8091 -2717,8267 ; -2893,8619 -3069,8443 ; -2717,8619 -2893,8443 -2893,8267 ; -2321,8091 -2145,8267 ; -2321,8443 -2145,8619 ; -2233,8091 -2057,8267 ; -2233,8443 -2057,8619 ; -2145,8091 -1969,8267 ; -2057,8091 -1969,8179 ; -2057,8443 -1969,8531 ; -1859,8267 3685,8267 ; -1859,8443 3685,8443 ; -1815,8619 -1859,8619 3685,8619 ; -1793,-2909 -1793,-2689 ; -1793,10071 -1793,10291 ; -1397,8091 -1397,8971 ; -935,8091 -935,8971 ; -451,8091 -451,8971 ; 121,8091 121,8971 ; 121,8740 3685,8740 ; 121,8861 3685,8861 ; 517,-2909 517,-2689 ; 517,10071 517,10291 ; 1309,8091 1309,8861 ; 2497,8091 2497,8861 ; 2827,-2909 2827,-2689 ; 2827,10071 2827,10291 ; 5137,-2909 5137,-2689 ; 5137,10071 5137,10291 ; 7447,-2909 7447,-2689 ; 7447,10071 7447,10291 ; 9757,-2909 9757,-2689 ; 9757,8971 9757,10071 9757,10291 ; 10197,8971 10197,9851 ; 12067,-2909 12067,-2689 ; 12067,10071 12067,10291 ; 12397,8971 12397,9851 ; 12507,-2689 12507,-2029 ; 13277,8971 13277,9851 ; 14157,391 14377,391 ; 14157,3691 14377,3691 ; 14157,6991 14377,6991 ; -3069,8091 -3069,8267 -1969,8267 ; -3069,8091 -1969,8091 -1969,8267 ; -3069,8091 -2893,8267 ; -3069,8443 -3069,8619 -1969,8619 ; -3069,8443 -1969,8443 -1969,8619 ; -2893,8267 -2145,8267 ; -2145,8267 -2145,8443 -1969,8619 ; -3883,-2689 -3883,10071 14157,10071 14157,-2689 -3883,-2689 ; -1859,8091 -1859,8971 3685,8971 3685,8091 -1859,8091
  lines w2.79: 9757,-2689 9757,-1369 14157,-1369 ; 10637,-2689 10637,-1809 ; 10637,-2249 14157,-2249 ; 10637,-2029 14157,-2029 ; 12507,-2469 14157,-2469 ; 14062.53,-1809 11391.47,-1809 9757,-1809 14157,-1809 ; -4103,-2909 14377,-2909 14377,10291 -4103,10291 -4103,-2853.12 -4103,-2909
  lines w2.85: 9757,9191 14157,9191 ; 9757,9851 14157,9851 ; 10470.9,8971 9757,8971 14157,8971 14103.1,8971 ; 10470.9,9411 9757,9411 14157,9411 ; 10470.9,9631 9757,9631 14157,9631
  lines w10: 2530.29,620.94 2596.96,620.94 2596.96,687.61 2530.29,687.61 2530.29,620.94 ; 2530.29,770.94 2563.62,787.61 2596.96,770.94 2580.29,804.28 2596.96,837.61 2563.62,820.94 2530.29,837.61 2546.96,804.28 2530.29,770.94 ; 2530.29,987.61 2596.96,987.61 2563.62,920.94 2530.29,987.61 ; 2530.29,1104.28 2563.62,1070.94 2596.96,1104.28 2563.62,1137.61 2530.29,1104.28 ; 2530.29,1237.61 2546.96,1237.61 2563.62,1220.94 2580.29,1237.61 2596.96,1237.61 2580.29,1254.28 2596.96,1270.94 2580.29,1270.94 2563.62,1287.61 2546.96,1270.94 2530.29,1270.94 2546.96,1254.28 2530.29,1237.61 ; 2530.29,1520.94 2596.96,1520.94 2596.96,1587.61 2530.29,1587.61 2530.29,1520.94 ; 2543.62,1534.28 2583.62,1534.28 2583.62,1574.28 2543.62,1574.28 2543.62,1534.28
  lines w15: 2470.5,575.94 7175.23,575.94 ; 2470.5,1775.94 7175.23,1775.94 ; 3021.38,425.94 3021.38,1925.94 ; 3611.22,425.94 3611.22,1925.94 ; 4780.88,425.94 4780.88,1925.94 ; 5286.75,425.94 5286.75,1925.94 ; 6020.56,425.94 6020.56,1925.94 ; 2470.5,425.94 7175.23,425.94 7175.23,1925.94 2470.5,1925.94 2470.5,425.94
  text "1" at -2945.8,10134.43 h139.7
  text "2" at -635.8,10134.43 h139.7
  text "3" at 1674.2,10134.43 h139.7
  text "4" at 3984.2,10134.43 h139.7
  text "5" at 6294.2,10134.43 h139.7
  text "6" at 8604.2,10134.43 h139.7
  text "7" at 10914.2,10134.43 h139.7
  text "8" at 13224.2,10134.43 h139.7
  text "REVISIONS" at 11473,9892.43 h139.7
  text "REV" at 9900.16,9722.37 h52.53
  text "ACTION" at 10327.8,9717.68 h52.53
  text "DATE" at 12707.1,9717.68 h52.53
  text "AUTH" at 13587.1,9717.68 h52.53
  text "First release" at 10327.8,9501.68 h52.53
  text "2017/05/25" at 12499.21,9497.68 h52.53
  text "Amy Kuang" at 13525,9496 h52.53
  text "A" at 9882,9494 h52.53
  text "C" at 9943,9284 h52.53
  text "2017/09/05" at 12505.21,9282.68 h52.53
  text "second release" at 10329.8,9275.68 h52.53
  text "Amy Kuang" at 13534,9266 h52.53
  text "LAYERS LAMINATION & IMPENDANCE  CONTROL" at -1793,9078.43 h139.7
  text "IMPEDANCE" at 1678.08,8887.49 h52.53
  text "LAYERS STACKUP" at -2796.95,8771.68 h52.53
  text "LAYER" at -1712.26,8771.68 h52.53
  text "MATERIAL" at -1347.82,8771.68 h52.53
  text "THICKNESS" at -911.01,8771.68 h52.53
  text "LAYER TYPE" at -408.2,8771.68 h52.53
  text "SINGLE 50ohm+/-10%" at 258.74,8755.49 h52.53
  text "DIFFERENCE 90ohm-/+10%" at 1343.92,8755.49 h52.53
  text "DIFFERENCE 100ohm-/+10%" at 2506.22,8755.49 h52.53
  text "Line width(mil)" at 335.85,8645.49 h52.53
  text "Line width/Space(mil)" at 1347.63,8645.49 h52.53
  text "Line width/Space(mil)" at 2557.63,8645.49 h52.53
  text "D" at -4045.8,8594.43 h139.7
  text "D" at 14214.2,8594.43 h139.7
  text "COPPER" at -1297.44,8507.68 h52.53
  text "1 OZ" at -763.07,8507.68 h52.53
  text "ROUTING" at -332.63,8507.68 h52.53
  text "5mil" at 622.31,8491.49 h52.53
  text "mil" at 1837,8487 h52.53
  text "mil" at 3047,8487 h52.53
  text "TOP" at -2585.88,8485.68 h52.53
  text "TOP" at -1705.88,8485.68 h52.53
  text "FR4" at -1221.88,8331.68 h52.53
  text "4.3mil" at -813.44,8331.68 h52.53
  text "PREPREG" at -1812.51,8315.49 h52.53
  text "PREPREG" at -2686.63,8309.68 h52.53
  text "COPPER" at -1287,8157 h52.53
  text "1 OZ" at -763.07,8155.68 h52.53
  text "PLANE" at -282.26,8155.68 h52.53
  text "5mil" at 622.31,8141.49 h52.53
  text "BOTTOM" at -2666.8,8139.49 h52.53
  text "BOTTOM" at -1786.8,8139.49 h52.53
  text "NOTE" at 9779,7849 h139.7
  text "THE TOTAL THICKNESS:" at -1882,7685 h139.7
  text "1.6MM+/-10%" at 1108.68,7643.57 h139.69
  text "1. ACCEPTABILITY:" at 9777.48,7561.68 h52.53
  text "PRINTED WIRING BOARD SHALL MEET THE REQUIREMENTS OF IPC- 6012C CLASS 2." at 9982.47,7451.68 h52.53
  text "2. MATERIAL:" at 9777.48,7231.68 h52.53
  text "GLASS EPOXY FR-4 FIRE RETARDANT AND UL 94V-0 RATING MATERIAL SHOULD MEET" at 9982.47,7121.68 h52.53
  text "IPC-4101C" at 9982.47,7011.68 h52.53
  text "3. FABRICATION REQUIREMENTS:" at 9777.48,6791.68 h52.53
  text "A). FAB TO MEET THE REQUIREMENTS PER IPC-A-600, CLASS 2" at 9982.47,6681.68 h52.53
  text "B). ALL ARTWORK OR ELECTRONIC DATA MAY BE ADJUSTED BY THE BOARD" at 9982.47,6571.68 h52.53
  text "MANUFACTURER TO COMPENSATE FOR MANUFACTURING PROCESS TOLERANCES," at 10180.47,6461.68 h52.53
  text "ADDITION OF FILLETS TEARDROPS AT LINE / PAD INTERFACE IS PREFERRED." at 10180.47,6351.68 h52.53
  text "THIEVING IS ALLOWED TO COMPENSATE FOR HIGH COPPER DENSITY AREAS" at 10180.47,6241.68 h52.53
  text "C). FABRICATE ACCORDING TO THE FILES PART NO:" at 9982.47,6131.68 h52.53
  text "1001001000655_STM8L_GERBER_RevC FILE FOR MANUFACTURING" at 10180.47,6021.68 h52.53
  text "D). SOLDER MASK COLOR  WHITE,SILKSCREEN COLOR BLUE INK PANTONE 2955" at 9982.47,5911.68 h52.53
  text "E). FINISH ENIG" at 9982.47,5801.68 h52.53
  text "4. FABRICATION TOLERANCE:" at 9777.48,5581.68 h52.53
  text "A). WIRE WIDTH TOLERANCE INTERNAL CONTROL STANDARD +/-20%" at 9982.47,5471.68 h52.53
  text "B). PTH  DIAMETER TOLERANCE +/-0.076mm,NPTH DIAMETER TOLERANCE +/-0.05mm" at 9982.47,5361.68 h52.53
  text "C" at -4045.8,5294.43 h139.7
  text "C" at 14214.2,5294.43 h139.7
  text "C). ALL OUTER LAYER PADS REQUIRE +/-0.05mm TOLERANCE." at 9982.47,5251.68 h52.53
  text "D). LAYER REGISTRATION BETWEEN ADJACENT LAYER MAXIMUN 150um, THE INTERLAYER" at 9982.47,5141.68 h52.53
  text "DIELECTRIC THICKNESS TOLERANCE +/-15%" at 10180.47,5031.68 h52.53
  text "E). THICKNESS IS LESS THAN 1mm PCB TO A TOLERANCE OF +/-0.1mm,THICKNESS IS" at 9982.47,4921.68 h52.53
  text "GREATER THAN OR EQUAL TO 1mm PCB TO A TOLERANCE OF +/-10%" at 10180.47,4811.68 h52.53
  text "5. SOLDER MASK:" at 9777.48,4591.68 h52.53
  text "A). MATERIALS IN ACCORDANCE WITH IPC-SM-840E CLASS T STANDARDS AND ROHS" at 9982.47,4481.68 h52.53
  text "REQUIREMENTS" at 10180.47,4371.68 h52.53
  text "B). SOLDER MASK BOTH PRIMARY AND SECONDARY SIDES, THE ADHESION OF SOLDER" at 9982.47,4261.68 h52.53
  text "MASK MEET THE REQUIREMENTS OF IPC-A-600F LEVEL 2" at 10180.47,4151.68 h52.53
  text "C). SOLDER MASK COVERAGE ON THE MIDDLE OF THE COPPER WIRE MINIMUM 10um,EDGE" at 9982.47,4041.68 h52.53
  text "COVERAGE OF THE COPPER WIRE MINIMUM 4um, SOLDER MASK MISREGISTRATION" at 10180.47,3931.68 h52.53
  text "MAXIM 2.5mil" at 10180.47,3821.68 h52.53
  text "D). ALL HOLES WITH SOLDER MASK COVERED IN THE GERBER SHOULD BE PULGED" at 9982.47,3711.68 h52.53
  text "E). SOLDER MASK BRIDGE BETWEEN PADS SHOULD BE MINIMUM 0.10mm" at 9982.47,3601.68 h52.53
  text "6. FINISH:" at 9777.48,3381.68 h52.53
  text "A). ENIG, GOLD THICKNESS IS 0.05 um ~0.23um,NICKEL THICKNESS IS 3 um ~6 um." at 9982.47,3271.68 h52.53
  text "B). OSP, THE OSP COATING THICKNESS IS 0.2 um ~0.5um." at 9982.47,3161.68 h52.53
  text "C). LF HASL, Sn THICKNESS IS 1 um ~40um ." at 9982.47,3051.68 h52.53
  text "7. SILKSCREEN:" at 9777.48,2831.68 h52.53
  text "A). PRIMARY AND SECONDARY SIDES USING A GLOSSY , NON-CONDUCTIVE, RoHS COMPLIANT," at 9982.47,2721.68 h52.53
  text "EPOXY BASED INK" at 10180.47,2611.68 h52.53
  text "B). NO SILKSCREEN ALLOWED ON PADS OR IN HOLES" at 9982.47,2501.68 h52.53
  text "C). MANUFACTUREERS CAN ADD SYMBOL IN SILKSCREEN LAYER OR SOLDER MASK LAYER," at 9982.47,2391.68 h52.53
  text "ALLOW TO INCREASE SYMBOL :ASSEMBLY REF , DATE CODE, LEAD-FREE SYMBOL, UL FILE" at 10180.47,2281.68 h52.53
  text "NUMBER,UL TYPE, UL SYMBOL AND FIRE RATING,NO LIST DOES NOT ALLOW TO INCREASE." at 10180.47,2171.68 h52.53
  text "B" at -4045.8,1994.43 h139.7
  text "B" at 14214.2,1994.43 h139.7
  text "8. BOW AND TWIST:" at 9777.48,1951.68 h52.53
  text "MAX BOW & TWIST OF PCB SHALL NOT EXCEED 0.75% OF MAXIMUN DIMENSION," at 9982.47,1841.68 h52.53
  text "Symbol" at 2560.5,1820.94 h72
  text "Count" at 3066.38,1820.94 h72
  text "Hole Size" at 3656.22,1820.94 h72
  text "Plated" at 4825.88,1820.94 h72
  text "Hole Type" at 5331.75,1820.94 h72
  text "Hole Length" at 6065.56,1820.94 h72
  text "MEASUREMENT METHOD IN 2.4.22 OF IPC-TM-650 IS FOR REFERENCE" at 9982.47,1731.68 h52.53
  text "4" at 3066.38,1670.94 h60
  text "7,87mil (0,200mm)" at 3656.22,1670.94 h60
  text "PTH" at 4825.88,1670.94 h60
  text "Round" at 5331.75,1670.94 h60
  text "-" at 6065.56,1670.94 h60
  text "474" at 3066.38,1520.94 h60
  text "10,00mil (0,254mm)" at 3656.22,1520.94 h60
  text "PTH" at 4825.88,1520.94 h60
  text "Round" at 5331.75,1520.94 h60
  text "-" at 6065.56,1520.94 h60
  text "9. MEASUREMENTS:" at 9777.48,1511.68 h52.53
  text "INTERPRET ALL DIMENSIONS AND TOLERANCES PER IPC-D-300G, CLASS B AND ALL" at 9982.47,1401.68 h52.53
  text "12" at 3066.38,1370.94 h60
  text "12,00mil (0,305mm)" at 3656.22,1370.94 h60
  text "PTH" at 4825.88,1370.94 h60
  text "Round" at 5331.75,1370.94 h60
  text "-" at 6065.56,1370.94 h60
  text "DIMENSIONS ARE METRIC, DIMENSIONS ARE AFTER ETCHING AND PLATING." at 9982.47,1291.68 h52.53
  text "2" at 3066.38,1220.94 h60
  text "23,62mil (0,600mm)" at 3656.22,1220.94 h60
  text "PTH" at 4825.88,1220.94 h60
  text "Slot" at 5331.75,1220.94 h60
  text "41,34mil (1,050mm)" at 6065.56,1220.94 h60
  text "2" at 3066.38,1070.94 h60
  text "23,62mil (0,600mm)" at 3656.22,1070.94 h60
  text "PTH" at 4825.88,1070.94 h60
  text "Slot" at 5331.75,1070.94 h60
  text "47,24mil (1,200mm)" at 6065.56,1070.94 h60
  text "10.ENVIRONMENTAL:" at 9777.48,1071.68 h52.53
  text "THE  PCB SUPPLIER SHALL PROVIDE A SIGNED CERTIFICATE OF COMPLIANCE BY" at 9982.47,961.68 h52.53
  text "88" at 3066.38,920.94 h60
  text "37,40mil (0,950mm)" at 3656.22,920.94 h60
  text "PTH" at 4825.88,920.94 h60
  text "Round" at 5331.75,920.94 h60
  text "-" at 6065.56,920.94 h60
  text "AUTHORIZED QA  REPRESENTATIVE. THE BASE MATERIAL OF PCB SHALL NOT CONTAIN THE" at 9982.47,851.68 h52.53
  text "32" at 3066.38,770.94 h60
  text "40,16mil (1,020mm)" at 3656.22,770.94 h60
  text "PTH" at 4825.88,770.94 h60
  text "Round" at 5331.75,770.94 h60
  text "-" at 6065.56,770.94 h60
  text "BANNED SUBSTANCES LISTED IN THE CERTIFICATE OF COMPLIANCE." at 9982.47,741.68 h52.53
  text "3" at 3066.38,620.94 h60
  text "125,98mil (3,200mm)" at 3656.22,620.94 h60
  text "NPTH" at 4825.88,620.94 h60
  text "Round" at 5331.75,620.94 h60
  text "-" at 6065.56,620.94 h60
  text "617 Total" at 3066.38,470.94 h60
  text "Slot definitions :" at 2560.5,325.97 h60
  text "Routed Path Length" at 3593.19,325.97 h60
  text "= Calculated from tool start centre position to tool end centre position." at 4695.86,325.97 h60
  text "Hole Length" at 3593.19,225.99 h60
  text "= Routed Path Length + Tool Size = Slot length as defined in the PCB layout" at 4285.99,225.99 h60
  text "A" at -4045.8,-1305.57 h139.7
  text "A" at 14214.2,-1305.57 h139.7
  text "Embest Technology co.,Ltd." at 10144.2,-1635.57 h139.7
  text "STM8L" at 11058,-1940 h52.53
  text "TITLE:" at 10692.45,-1942.32 h52.53
  text "Andy Meng" at 13218.1,-2159.32 h52.53
  text "PART NUMBER:" at 10704.56,-2162.32 h52.53
  text "ELEC ENGR:" at 12565.21,-2162.32 h52.53
  text "1001001000655" at 11440.1,-2164.32 h52.53
  text "C" at 12920.1,-2380.32 h52.53
  text "ADD:" at 10705.1,-2382.32 h52.53
  text "REV:" at 12565.75,-2382.32 h52.53
  text "www.embest-tech.com" at 10705.64,-2542.04 h52.53
  text "DATE:" at 12573,-2601 h52.53
  text "2017/09/05" at 12917.21,-2601.32 h52.53
  text "1" at -2945.8,-2845.57 h139.7
  text "2" at -635.8,-2845.57 h139.7
  text "3" at 1674.2,-2845.57 h139.7
  text "4" at 3984.2,-2845.57 h139.7
  text "5" at 6294.2,-2845.57 h139.7
  text "6" at 8604.2,-2845.57 h139.7
  text "7" at 10914.2,-2845.57 h139.7
  text "8" at 13224.2,-2845.57 h139.7

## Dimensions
-1649.21,3149.61 to -1196.46,-98.43 on M2-Board Dimensions
-1727.95,3061 to 1027.95,3061 on M2-Board Dimensions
